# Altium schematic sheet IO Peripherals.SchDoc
size A4; DocumentNumber: 6; Revision: D.1(PCB.SCH); SheetNumber: 6; SheetTotal: 6
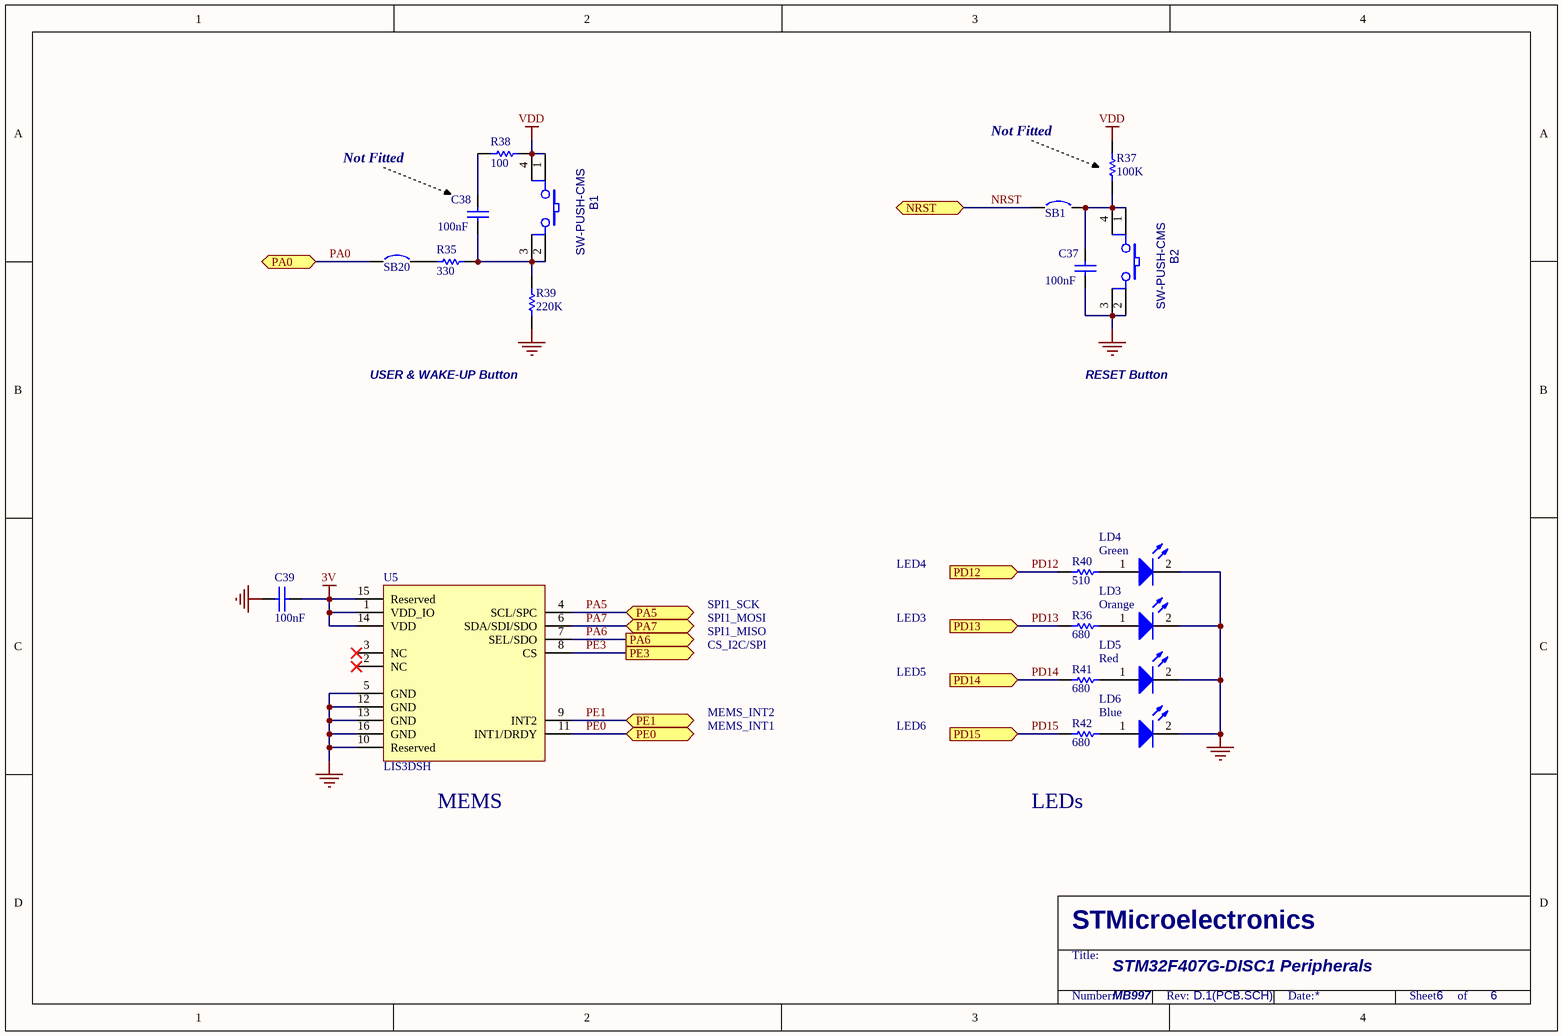
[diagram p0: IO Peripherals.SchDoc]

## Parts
B1  SW-PUSH-CMS  [BP1CMS]
B2  SW-PUSH-CMS  [BP1CMS]
C37  100nF  [0603C]
C38  100nF  [0603C]
C39  100nF  [0402C]
LD3  Orange  [0603D]
LD4  Green  [0603D]
LD5  Red  [0603D]
LD6  Blue  [0603D]
R35  330  [0402R]
R36  680  [0603R]
R37  100K  [0402R]
R38  100  [0402R]
R39  220K  [0603R]
R40  510  [0603R]
R41  680  [0603R]
R42  680  [0603R]
SB1  Circuit Breaker  [JP2_SMD]  (value not drawn)
SB20  Circuit Breaker  [JP2_SMD]  (value not drawn)
U5  LIS3DSH  [LGA16(3*3)]

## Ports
NRST, PA0, PA5 (bidir), PA6 (out), PA7 (bidir), PD12 (in), PD13 (in), PD14 (in), PD15 (in), PE0, PE1, PE3 (out)

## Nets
3V: C39.2 U5.1(VDD_IO) U5.14(VDD) U5.15(Reserved)
GND: B2.2 B2.3 C37.1 C39.1 LD3.2(K) LD4.2(K) LD5.2(K) LD6.2(K) R39.1 U5.5(GND) U5.10(Reserved) U5.12(GND) U5.13(GND) U5.16(GND)
VDD: B1.1 B1.4 R37.2 R38.2
NRST: SB1.1 ; port NRST
PA0: SB20.1 ; port PA0
PA5: U5.4(SCL/SPC) ; port PA5
PA6: U5.7(SEL/SDO) ; port PA6
PA7: U5.6(SDA/SDI/SDO) ; port PA7
PD12: R40.2 ; port PD12
PD13: R36.2 ; port PD13
PD14: R41.2 ; port PD14
PD15: R42.2 ; port PD15
PE0: U5.11(INT1/DRDY) ; port PE0
PE1: U5.9(INT2) ; port PE1
PE3: U5.8(CS) ; port PE3
NetB1_2: B1.2 B1.3 C38.1 R35.2 R39.2
NetB2_1: B2.1 B2.4 C37.2 R37.1 SB1.2
NetC38_2: C38.2 R38.1
NetLD3_1: LD3.1(A) R36.1
NetLD4_1: LD4.1(A) R40.1
NetLD5_1: LD5.1(A) R41.1
NetLD6_1: LD6.1(A) R42.1
NetR35_1: R35.1 SB20.2

Not connected (* = marked no-connect by the designer): U5 2(NC)* 3(NC)*

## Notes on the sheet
- Not Fitted
- USER & WAKE-UP Button
- RESET Button
- LED4
- SPI1_MOSI
- SPI1_SCK
- SPI1_MISO
- CS_I2C/SPI
- LED3
- MEMS_INT2
- LED5
- MEMS_INT1
- LED6
- (near U5) MEMS
- LEDs
- STM32F407G-DISC1 Peripherals
- MB997

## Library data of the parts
B1 B2 = SW-PUSH-CMS: Non-Open Push-Button 0.1A 24V; Manuf_1: FARNELL; Manuf_Part_1: 535-930; Ref St: 9180120; cap_dec: ---
C37 C39 = CAP: Capacitor
C38 = CAP: Capacitor; Fitted: NO
LD3-LD6 = LED2: Typical RED, GREEN, YELLOW, AMBER GaAs LED
R35 = res1: Resistor
R36 R40-R42 = Res1: Resistor; Value: 1K
R37 = res1: Resistor; Fitted: NO
R38 = res1: Resistor; Value: 330
R39 = res1: Resistor; Value: 10K
SB1 SB20 = Circuit Breaker: Solder: YES
U5 = LIS3DSH: MEMS motion sensor 3-axis - ±2g/±4g/±6g/±8g/±16g digital output accelerometer; Manuf_1: STM; Manuf_Part_1: LIS3DSHTR; Provided: ST; Description: MEMS motion sensor 3-axis - ±2g to ±16g digital output accelerometer; ref St: to be created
